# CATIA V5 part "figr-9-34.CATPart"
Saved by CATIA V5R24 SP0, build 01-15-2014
Part number: Part1
Bounding box of the stored display mesh (mm): x -250 to 0, y -60 to 60, z 0 to 100
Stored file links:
  D:\KAVITA\CATIA V5-6R2014 Project_ Kavita\CATIA V5-6R2014_partfiles\Partfiles\c09_catia_v5-6r2014_prt\figr-9-34.CATPart
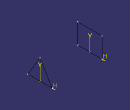
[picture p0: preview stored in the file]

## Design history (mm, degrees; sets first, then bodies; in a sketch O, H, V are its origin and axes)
Body1 (main body)
  Sketch1 on yz-plane, origin (0, 0, 0), H (0, 1, 0), V (0, 0, 1)
    point P1 (-60, 0)
    line L1 (-60, 0) -> (0, 100)
    point P2 (0, 100)
    line L2 (0, 100) -> (60, 0)
    point P3 (60, 0)
    line L3 (60, 0) -> (-60, 0)
    coincidence: P1 H, P2 V, P3 H
    horizontal: L3 H
    midpoint: O L3
  Sketch2, origin (-250, 0, 0), H (0, 1, 0), V (0, 0, 1)
    point P1 (-60, 0)
    line L1 (-60, 0) -> (60, 0)
    line L2 (60, 0) -> (60, 100)
    line L3 (60, 100) -> (-60, 100)
    line L4 (-60, 100) -> (-60, 0)
    coincidence: P1 H
    horizontal: L1 H, L3 H
    vertical: L2 V, L4 V
  Loft1: Sections (Sketch1; Sketch2), SectionCouplingPoints ({coupling CouplingPoints (vertex [element of Sketch1 | element of Sketch1]; vertex [element of Sketch2 | element of Sketch2])}; {coupling CouplingPoints (vertex [element of Sketch1 | element of Sketch1]; vertex [element of Sketch2 | element of Sketch2])}; {coupling CouplingPoints (vertex [element of Sketch1 | element of Sketch1]; vertex [element of Sketch2 | element of Sketch2])})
